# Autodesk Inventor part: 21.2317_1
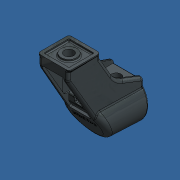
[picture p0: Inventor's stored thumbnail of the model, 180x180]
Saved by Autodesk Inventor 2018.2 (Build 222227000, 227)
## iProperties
Created: 2014-10
Part Number: 21.2317_1
Material: ABS Plastik
Document SubType Name: Modeling
Designer: amoles
Density: 1.06 g/cm^3
Appearance: Default
Description: HANDLE GP PLASTIC GASE
Author: amoles
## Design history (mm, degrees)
feature "45D"
body "Solid1"
